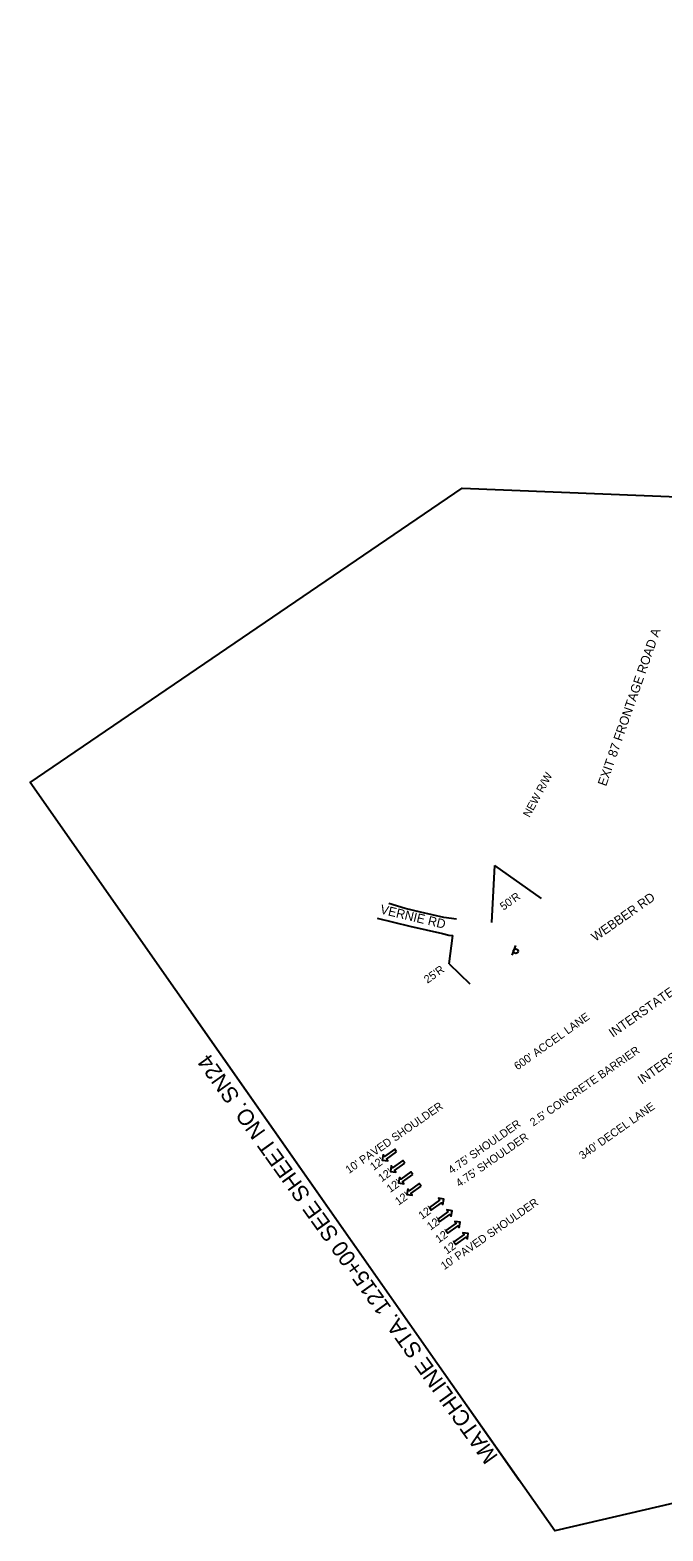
# Model space of a CAD drawing. Extents: x 1770940 to 1772558, y 1178099 to 1179642.
# Drawn here: x 1770940 to 1771494, y 1178099 to 1179412 of the extents above; entities that cross this region are included whole.
import ezdxf

# ---------------------------------------------------------------- set-up
doc = ezdxf.new("R2010")
doc.units = 0
for name, color, linetype in [('RD_EX_Road', 7, 'Continuous'), ('RD_PD_Final_LnLine', 7, 'Continuous'), ('RD_PD_Final_TX', 7, 'Continuous'), ('RD_PD_RW_TX', 7, 'Continuous'), ('RD_SHT_MatchLine', 7, 'Continuous'), ('RD_SHT_ShtClip', 7, 'Continuous'), ('RD_TX_RoadID', 7, 'Continuous'), ('SN_P_Signs', 7, 'Continuous')]:
    doc.layers.add(name, color=color, linetype=linetype)

# ---------------------------------------------------------------- blocks, each defined once
blk = doc.blocks.new('SARRW2')
at = {"layer": 'RD_PD_Final_LnLine'}
blk.add_lwpolyline([(-12, 1.2), (-12, -1.2), (-2.8, -1.2), (-2.8, -2.8), (0, 0), (-2.8, 2.8), (-2.8, 1.2)], close=True, dxfattribs=at)

msp = doc.modelspace()

# ---------------------------------------------------------------- linework, layer by layer
at = {"layer": 'RD_EX_Road'}
for points in [[(1771312.9, 1178634.1), (1771301.9, 1178635.6), (1771281.5, 1178640.3), (1771268, 1178643.6), (1771253.9, 1178647.9)], [(1771243.6, 1178635), (1771272.1, 1178628), (1771300.6, 1178621.5), (1771306.2, 1178620.2), (1771309.7, 1178619.8)]]:
    msp.add_lwpolyline(points, dxfattribs=at)
at = {"layer": 'RD_PD_Final_TX'}
for p, q in [((1771346.3, 1178681.2), (1771343.6, 1178631.3)), ((1771346.3, 1178681.2), (1771386.9, 1178652.1)), ((1771306.7, 1178595), (1771309.7, 1178619.8)), ((1771306.7, 1178595), (1771324.7, 1178577.6))]:
    msp.add_line(p, q, dxfattribs=at)
at = {"layer": 'RD_SHT_MatchLine'}
msp.add_lwpolyline([(1771367.9, 1178143.2), (1771080.9, 1178552.6)], dxfattribs=at)
at = {"layer": 'RD_SHT_ShtClip'}
msp.add_lwpolyline([(1771296.2, 1178245.5), (1771109.1, 1178512.4), (1770940, 1178753.7), (1771317.8, 1179011.2), (1771643.5, 1178998.1), (1772001.7, 1179411.7), (1772162.5, 1179241.9), (1772385.8, 1179331.3), (1772558.1, 1179023.3), (1772212.5, 1178884.9), (1772278.1, 1178588), (1772022.9, 1178414.1), (1771928, 1178222.3), (1771398.9, 1178099.1)], close=True, dxfattribs=at)
at = {"layer": 'SN_P_Signs'}
msp.add_line((1771364.5, 1178611.1), (1771361.4, 1178602.7), dxfattribs=at)
msp.add_circle((1771364.8, 1178606.2), 2, dxfattribs=at)

# ---------------------------------------------------------------- block references
at = {"layer": 'RD_PD_Final_LnLine', "xscale": 1.1999999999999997}
for p, yscale, rotation in [((1771248.1, 1178423.5), 1.2000000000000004, -144.38650217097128), ((1771255.2, 1178413.6), 1.2000000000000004, -144.38650217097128), ((1771262.3, 1178403.6), 1.2000000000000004, -144.38650217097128), ((1771269.6, 1178393.4), 1.2000000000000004, -144.38650217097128), ((1771301.8, 1178389.3), 1.2, 35.61349782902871), ((1771309.1, 1178379.1), 1.2, 35.61349782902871), ((1771316.2, 1178369.1), 1.2, 35.61349782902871), ((1771323.3, 1178359.2), 1.2, 35.61349782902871)]:
    msp.add_blockref('SARRW2', p, dxfattribs=dict(at, yscale=yscale, rotation=rotation))

# ---------------------------------------------------------------- texts
at = {"layer": 'RD_PD_Final_TX'}
for s, rotation, p in [("50'R", 35.5173, (1771354.1, 1178641.5)), ("25'R", 35.5173, (1771287.6, 1178577.6)), ("600' ACCEL LANE", 35.5173, (1771366.4, 1178501.8)), ("2.5' CONCRETE BARRIER", 34.8311, (1771380.2, 1178452.7)), ("10' PAVED SHOULDER", 34.9248, (1771218.9, 1178411.2)), ("340' DECEL LANE", 35.1931, (1771423.2, 1178423.7)), ("4.75' SHOULDER", 34.8311, (1771308.7, 1178411)), ("4.75' SHOULDER", 34.8311, (1771315.4, 1178399.5)), ("12'", 35.6135, (1771240.5, 1178414)), ("12'", 35.6135, (1771247.6, 1178404)), ("12'", 35.6135, (1771255, 1178394.6)), ("12'", 35.6135, (1771262.3, 1178383.5)), ("10' PAVED SHOULDER", 34.8311, (1771302.3, 1178327.1)), ("12'", 35.6135, (1771282.8, 1178371.2)), ("12'", 35.6135, (1771290.2, 1178361.7)), ("12'", 35.6135, (1771297.5, 1178350.6)), ("12'", 35.6135, (1771304.6, 1178340.7))]:
    msp.add_text(s, height=7, rotation=rotation, dxfattribs=at).set_placement(p)
at = {"layer": 'RD_PD_RW_TX'}
msp.add_text('NEW R/W', height=7, rotation=61.5292, dxfattribs=at).set_placement((1771376.8, 1178722.6))
at = {"layer": 'RD_SHT_MatchLine'}
msp.add_text('MATCHLINE STA. 1215+00 SEE SHEET NO. SN24', height=14, rotation=125.6135, dxfattribs=at).set_placement((1771349.8, 1178164.3))
at = {"layer": 'RD_TX_RoadID'}
for s, rotation, p in [('EXIT 87 FRONTAGE ROAD A', 70.747, (1771443.8, 1178749.9)), ('WEBBER RD', 35.0349, (1771434.4, 1178614.3)), ('VERNIE RD', 346.5664, (1771245.7, 1178639.2)), ('INTERSTATE 85 SOUTHBOUND', 35.0884, (1771449.7, 1178530.4)), ('INTERSTATE 85 NORTHBOUND', 35.2829, (1771475, 1178489.3))]:
    msp.add_text(s, height=8, rotation=rotation, dxfattribs=at).set_placement(p)

doc.saveas('drawing.dxf')
